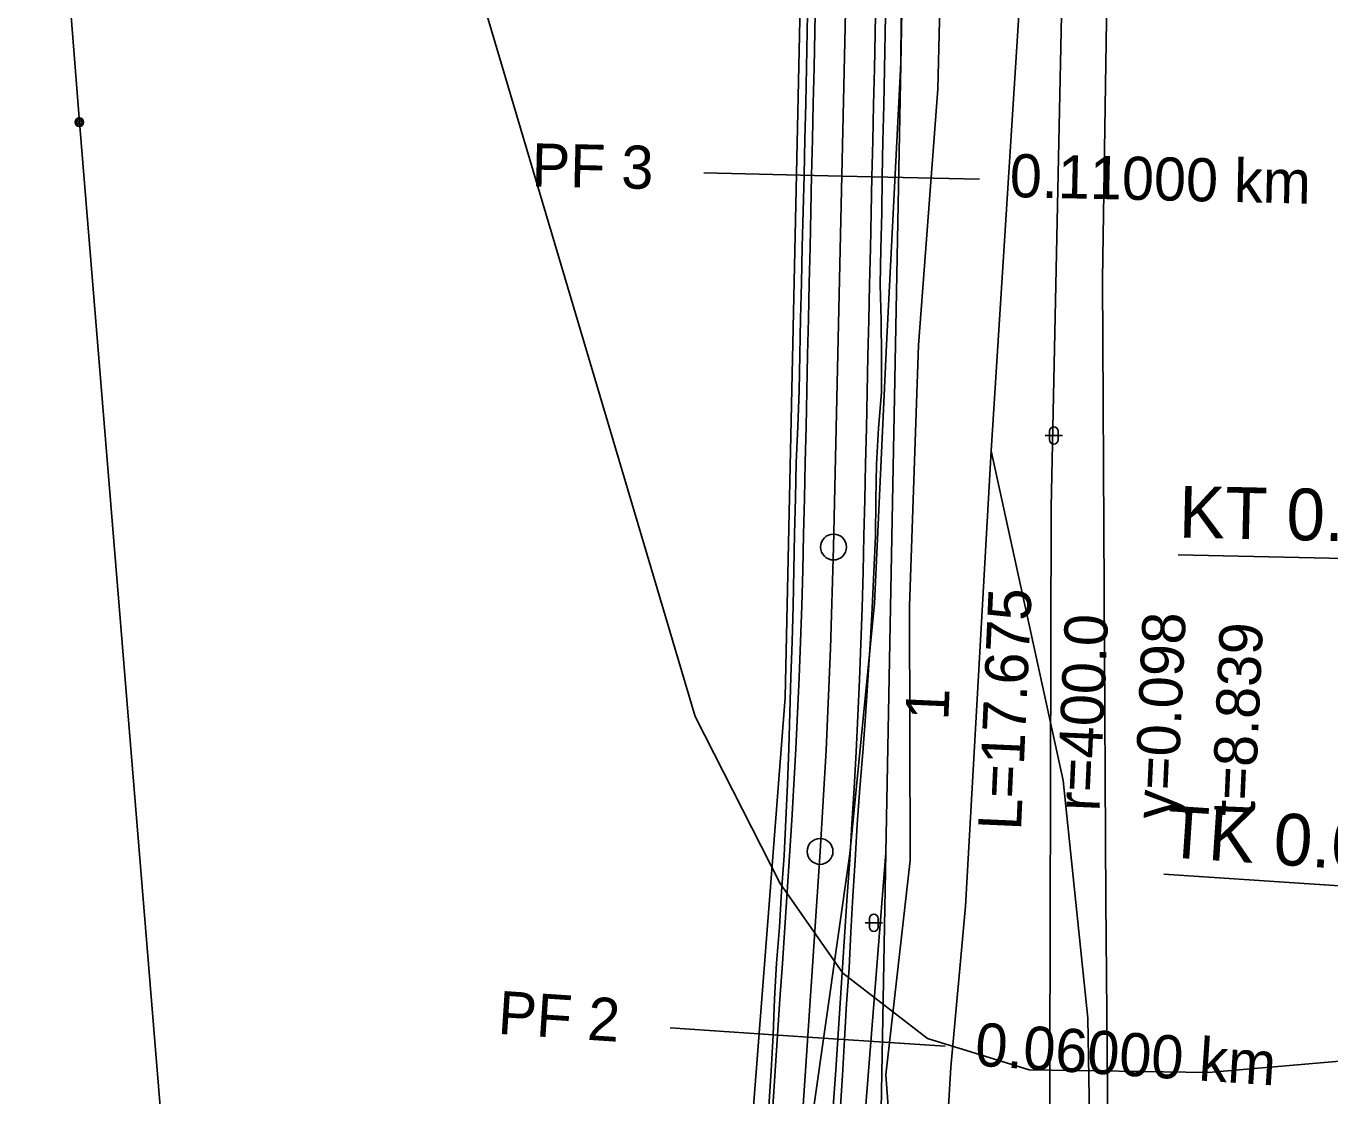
# Model space of a CAD drawing. Extents: x -555887 to -552101, y -1100251 to -1096546.
# Drawn here: x -554258.9 to -554183.3, y -1097524.4 to -1097462.4 of the extents above; entities that cross this region are included whole.
import ezdxf

# ---------------------------------------------------------------- set-up
doc = ezdxf.new("R2010")
doc.units = 0
for name, color, linetype in [('07_ELEKTRO', 7, 'Continuous'), ('PARCELY_cesty', 7, 'Continuous'), ('PARCELY_VHO', 7, 'Continuous'), ('POLYGONY_SITUACE_PF', 7, 'Continuous'), ('POLYGONY_SITUACE_PF_POPISY', 7, 'Continuous'), ('POLYGONY_SITUACE_PO', 7, 'Continuous'), ('vrstevnice', 7, 'Continuous'), ('ZSST', 7, 'Continuous')]:
    doc.layers.add(name, color=color, linetype=linetype)

msp = doc.modelspace()

# ---------------------------------------------------------------- linework, layer by layer
for p, q in [((-554192.078, -1097493.05), (-554170.991, -1097493.52)), ((-554192.901, -1097511.589), (-554171.855, -1097512.989))]:
    msp.add_line(p, q)
at = {"layer": '07_ELEKTRO'}
msp.add_lwpolyline([(-554275.08, -1097225.88), (-554271.756, -1097269.822), (-554266.687, -1097333.7), (-554260.452, -1097409.538), (-554255.844, -1097467.957), (-554251.063, -1097526.238), (-554246.538, -1097579.501), (-554242.27, -1097628.74), (-554241.833, -1097636.183)], dxfattribs=at)
at = {"layer": 'PARCELY_cesty'}
for points in [[(-554222.14, -1097577.67), (-554219.8, -1097564.758), (-554214.877, -1097501.328), (-554212.926, -1097411.068), (-554213.817, -1097399.017), (-554215.271, -1097391.192), (-554218.761, -1097379.641), (-554223.516, -1097368.495), (-554249.09, -1097318.382), (-554253.811, -1097305.999), (-554255.45, -1097297.231), (-554257.683, -1097277.564), (-554257.68, -1097272.957), (-554254.776, -1097263.93), (-554248.284, -1097256.84), (-554243.382, -1097252.09), (-554241.284, -1097247.986), (-554240.159, -1097243.281), (-554227.326, -1097094.829)], [(-554213.98, -1097572.5), (-554209.03, -1097510.351), (-554207.05, -1097405.63), (-554208.48, -1097387.75), (-554231.63, -1097341.59), (-554244.514, -1097316.349), (-554248.979, -1097304.638), (-554250.502, -1097296.489), (-554252.683, -1097277.283), (-554252.68, -1097273.743), (-554250.86, -1097269.06), (-554235.26, -1097250.21), (-554222.331, -1097095.103)]]:
    msp.add_lwpolyline(points, dxfattribs=at)
at = {"layer": 'PARCELY_VHO'}
msp.add_lwpolyline([(-554229.55, -1097316.95), (-554223.69, -1097322.98), (-554219.67, -1097327.12), (-554220.87, -1097341.28), (-554215.59, -1097358.86), (-554199.78, -1097386.16), (-554197.66, -1097405.58), (-554199.45, -1097490.3), (-554199.63, -1097570.97), (-554210.4, -1097572.11), (-554209.84, -1097554.02), (-554209.03, -1097510.351), (-554207.05, -1097405.63), (-554208.48, -1097387.75), (-554231.63, -1097341.59)], close=True, dxfattribs=at)
at = {"layer": 'POLYGONY_SITUACE_PF'}
for p, q in [((-554219.592, -1097470.904), (-554211.593, -1097471.082)), ((-554211.593, -1097471.082), (-554203.595, -1097471.261)), ((-554221.557, -1097520.503), (-554213.574, -1097521.034)), ((-554213.574, -1097521.034), (-554205.592, -1097521.566))]:
    msp.add_line(p, q, dxfattribs=at)
at = {"layer": 'POLYGONY_SITUACE_PO'}
for p, q in [((-554212.073, -1097492.604), (-554210.346, -1097415.119)), ((-554213.6, -1097462.702), (-554213.556, -1097460.619)), ((-554213.157, -1097462.712), (-554213.111, -1097460.629)), ((-554213.157, -1097462.712), (-554213.111, -1097460.629)), ((-554209.658, -1097462.79), (-554209.612, -1097460.707)), ((-554209.658, -1097462.79), (-554209.612, -1097460.707)), ((-554209.071, -1097462.803), (-554209.031, -1097460.72)), ((-554213.645, -1097464.785), (-554213.6, -1097462.702)), ((-554213.204, -1097464.795), (-554213.157, -1097462.712)), ((-554213.204, -1097464.795), (-554213.157, -1097462.712)), ((-554209.705, -1097464.873), (-554209.658, -1097462.79)), ((-554209.705, -1097464.873), (-554209.658, -1097462.79)), ((-554209.119, -1097464.886), (-554209.071, -1097462.803)), ((-554213.689, -1097466.868), (-554213.645, -1097464.785)), ((-554213.25, -1097466.878), (-554213.204, -1097464.795)), ((-554213.25, -1097466.878), (-554213.204, -1097464.795)), ((-554209.751, -1097466.956), (-554209.705, -1097464.873)), ((-554209.751, -1097466.956), (-554209.705, -1097464.873)), ((-554209.164, -1097466.969), (-554209.119, -1097464.886)), ((-554213.734, -1097468.951), (-554213.689, -1097466.868)), ((-554213.297, -1097468.961), (-554213.25, -1097466.878)), ((-554213.297, -1097468.961), (-554213.25, -1097466.878)), ((-554209.798, -1097469.038), (-554209.751, -1097466.956)), ((-554209.798, -1097469.038), (-554209.751, -1097466.956)), ((-554209.206, -1097469.052), (-554209.164, -1097466.969)), ((-554213.782, -1097471.034), (-554213.734, -1097468.951)), ((-554213.343, -1097471.043), (-554213.297, -1097468.961)), ((-554213.343, -1097471.043), (-554213.297, -1097468.961)), ((-554209.844, -1097471.121), (-554209.798, -1097469.038)), ((-554209.844, -1097471.121), (-554209.798, -1097469.038)), ((-554209.243, -1097471.135), (-554209.206, -1097469.052)), ((-554213.834, -1097473.116), (-554213.782, -1097471.034)), ((-554213.389, -1097473.126), (-554213.343, -1097471.043)), ((-554213.389, -1097473.126), (-554213.343, -1097471.043)), ((-554209.89, -1097473.204), (-554209.844, -1097471.121)), ((-554209.89, -1097473.204), (-554209.844, -1097471.121)), ((-554209.273, -1097473.218), (-554209.243, -1097471.135)), ((-554213.888, -1097475.199), (-554213.834, -1097473.116)), ((-554213.436, -1097475.209), (-554213.389, -1097473.126)), ((-554213.436, -1097475.209), (-554213.389, -1097473.126)), ((-554209.937, -1097475.287), (-554209.89, -1097473.204)), ((-554209.937, -1097475.287), (-554209.89, -1097473.204)), ((-554209.32, -1097475.301), (-554209.273, -1097473.218)), ((-554213.942, -1097477.282), (-554213.888, -1097475.199)), ((-554213.482, -1097477.292), (-554213.436, -1097475.209)), ((-554213.482, -1097477.292), (-554213.436, -1097475.209)), ((-554209.983, -1097477.37), (-554209.937, -1097475.287)), ((-554209.983, -1097477.37), (-554209.937, -1097475.287)), ((-554209.359, -1097477.384), (-554209.32, -1097475.301)), ((-554213.984, -1097479.364), (-554213.942, -1097477.282)), ((-554213.529, -1097479.375), (-554213.482, -1097477.292)), ((-554213.529, -1097479.375), (-554213.482, -1097477.292)), ((-554210.03, -1097479.453), (-554209.983, -1097477.37)), ((-554210.03, -1097479.453), (-554209.983, -1097477.37)), ((-554209.313, -1097479.469), (-554209.359, -1097477.384)), ((-554214.023, -1097481.447), (-554213.984, -1097479.364)), ((-554213.575, -1097481.457), (-554213.529, -1097479.375)), ((-554213.575, -1097481.457), (-554213.529, -1097479.375)), ((-554210.076, -1097481.535), (-554210.03, -1097479.453)), ((-554210.076, -1097481.535), (-554210.03, -1097479.453)), ((-554209.287, -1097481.553), (-554209.313, -1097479.469)), ((-554214.071, -1097483.53), (-554214.023, -1097481.447)), ((-554213.622, -1097483.54), (-554213.575, -1097481.457)), ((-554213.622, -1097483.54), (-554213.575, -1097481.457)), ((-554210.122, -1097483.618), (-554210.076, -1097481.535)), ((-554210.122, -1097483.618), (-554210.076, -1097481.535)), ((-554209.284, -1097483.637), (-554209.287, -1097481.553)), ((-554214.155, -1097485.612), (-554214.071, -1097483.53)), ((-554213.668, -1097485.623), (-554213.622, -1097483.54)), ((-554213.668, -1097485.623), (-554213.622, -1097483.54)), ((-554210.169, -1097485.701), (-554210.122, -1097483.618)), ((-554210.169, -1097485.701), (-554210.122, -1097483.618)), ((-554209.465, -1097485.717), (-554209.284, -1097483.637)), ((-554214.236, -1097487.694), (-554214.155, -1097485.612)), ((-554213.714, -1097487.706), (-554213.668, -1097485.623)), ((-554213.714, -1097487.706), (-554213.668, -1097485.623)), ((-554210.215, -1097487.784), (-554210.169, -1097485.701)), ((-554210.215, -1097487.784), (-554210.169, -1097485.701)), ((-554209.577, -1097487.798), (-554209.465, -1097485.717)), ((-554214.284, -1097489.777), (-554214.236, -1097487.694)), ((-554213.761, -1097489.789), (-554213.714, -1097487.706)), ((-554213.761, -1097489.789), (-554213.714, -1097487.706)), ((-554210.262, -1097489.867), (-554210.215, -1097487.784)), ((-554210.262, -1097489.867), (-554210.215, -1097487.784)), ((-554209.613, -1097489.881), (-554209.577, -1097487.798)), ((-554214.334, -1097491.86), (-554214.284, -1097489.777)), ((-554213.807, -1097491.871), (-554213.761, -1097489.789)), ((-554213.807, -1097491.871), (-554213.761, -1097489.789)), ((-554210.308, -1097491.949), (-554210.262, -1097489.867)), ((-554210.308, -1097491.949), (-554210.262, -1097489.867)), ((-554209.637, -1097491.964), (-554209.613, -1097489.881)), ((-554214.382, -1097493.935), (-554214.334, -1097491.86)), ((-554213.86, -1097493.948), (-554213.807, -1097491.871)), ((-554213.86, -1097493.948), (-554213.807, -1097491.871)), ((-554210.361, -1097494.038), (-554210.308, -1097491.949)), ((-554210.361, -1097494.038), (-554210.308, -1097491.949)), ((-554209.734, -1097494.054), (-554209.637, -1097491.964)), ((-554212.248, -1097498.493), (-554212.073, -1097492.604)), ((-554214.425, -1097496.006), (-554214.382, -1097493.935)), ((-554213.915, -1097496.022), (-554213.86, -1097493.948)), ((-554213.915, -1097496.022), (-554213.86, -1097493.948)), ((-554210.417, -1097496.13), (-554210.361, -1097494.038)), ((-554210.417, -1097496.13), (-554210.361, -1097494.038)), ((-554209.835, -1097496.148), (-554209.734, -1097494.054)), ((-554214.484, -1097498.077), (-554214.425, -1097496.006)), ((-554213.987, -1097498.095), (-554213.915, -1097496.022)), ((-554213.987, -1097498.095), (-554213.915, -1097496.022)), ((-554210.489, -1097498.221), (-554210.417, -1097496.13)), ((-554210.489, -1097498.221), (-554210.417, -1097496.13)), ((-554209.953, -1097498.24), (-554209.835, -1097496.148)), ((-554214.549, -1097500.147), (-554214.484, -1097498.077)), ((-554214.068, -1097500.167), (-554213.987, -1097498.095)), ((-554214.068, -1097500.167), (-554213.987, -1097498.095)), ((-554212.509, -1097504.379), (-554212.248, -1097498.493)), ((-554210.571, -1097500.312), (-554210.489, -1097498.221)), ((-554210.571, -1097500.312), (-554210.489, -1097498.221)), ((-554210.081, -1097500.332), (-554209.953, -1097498.24)), ((-554214.603, -1097502.219), (-554214.549, -1097500.147)), ((-554214.16, -1097502.239), (-554214.068, -1097500.167)), ((-554214.16, -1097502.239), (-554214.068, -1097500.167)), ((-554210.664, -1097502.402), (-554210.571, -1097500.312)), ((-554210.664, -1097502.402), (-554210.571, -1097500.312)), ((-554210.221, -1097502.423), (-554210.081, -1097500.332)), ((-554214.672, -1097504.29), (-554214.603, -1097502.219)), ((-554214.26, -1097504.311), (-554214.16, -1097502.239)), ((-554214.26, -1097504.311), (-554214.16, -1097502.239)), ((-554210.765, -1097504.492), (-554210.664, -1097502.402)), ((-554210.765, -1097504.492), (-554210.664, -1097502.402)), ((-554210.374, -1097504.513), (-554210.221, -1097502.423)), ((-554214.751, -1097506.361), (-554214.672, -1097504.29)), ((-554214.371, -1097506.382), (-554214.26, -1097504.311)), ((-554214.371, -1097506.382), (-554214.26, -1097504.311)), ((-554212.857, -1097510.26), (-554212.509, -1097504.379)), ((-554210.877, -1097506.582), (-554210.765, -1097504.492)), ((-554210.877, -1097506.582), (-554210.765, -1097504.492)), ((-554210.55, -1097506.6), (-554210.374, -1097504.513)), ((-554214.846, -1097508.431), (-554214.751, -1097506.361)), ((-554214.499, -1097508.453), (-554214.371, -1097506.382)), ((-554214.499, -1097508.453), (-554214.371, -1097506.382)), ((-554211.006, -1097508.67), (-554210.877, -1097506.582)), ((-554211.006, -1097508.67), (-554210.877, -1097506.582)), ((-554210.698, -1097508.689), (-554210.55, -1097506.6)), ((-554214.944, -1097510.503), (-554214.846, -1097508.431)), ((-554214.628, -1097510.524), (-554214.499, -1097508.453)), ((-554214.628, -1097510.524), (-554214.499, -1097508.453)), ((-554211.136, -1097510.757), (-554211.006, -1097508.67)), ((-554211.136, -1097510.757), (-554211.006, -1097508.67)), ((-554210.825, -1097510.778), (-554210.698, -1097508.689)), ((-554217.559, -1097580.902), (-554212.857, -1097510.26)), ((-554215.093, -1097512.581), (-554214.944, -1097510.503)), ((-554214.767, -1097512.603), (-554214.628, -1097510.524)), ((-554214.767, -1097512.603), (-554214.628, -1097510.524)), ((-554211.275, -1097512.836), (-554211.136, -1097510.757)), ((-554211.275, -1097512.836), (-554211.136, -1097510.757)), ((-554210.956, -1097512.857), (-554210.825, -1097510.778)), ((-554215.208, -1097514.662), (-554215.093, -1097512.581)), ((-554214.905, -1097514.682), (-554214.767, -1097512.603)), ((-554214.905, -1097514.682), (-554214.767, -1097512.603)), ((-554211.413, -1097514.914), (-554211.275, -1097512.836)), ((-554211.413, -1097514.914), (-554211.275, -1097512.836)), ((-554211.075, -1097514.937), (-554210.956, -1097512.857)), ((-554215.379, -1097516.738), (-554215.208, -1097514.662)), ((-554215.044, -1097516.761), (-554214.905, -1097514.682)), ((-554215.044, -1097516.761), (-554214.905, -1097514.682)), ((-554211.551, -1097516.993), (-554211.413, -1097514.914)), ((-554211.551, -1097516.993), (-554211.413, -1097514.914)), ((-554211.165, -1097517.019), (-554211.075, -1097514.937)), ((-554215.495, -1097518.819), (-554215.379, -1097516.738)), ((-554215.182, -1097518.839), (-554215.044, -1097516.761)), ((-554215.182, -1097518.839), (-554215.044, -1097516.761)), ((-554211.69, -1097519.072), (-554211.551, -1097516.993)), ((-554211.69, -1097519.072), (-554211.551, -1097516.993)), ((-554211.326, -1097519.096), (-554211.165, -1097517.019)), ((-554215.582, -1097520.901), (-554215.495, -1097518.819)), ((-554215.32, -1097520.918), (-554215.182, -1097518.839)), ((-554215.32, -1097520.918), (-554215.182, -1097518.839)), ((-554211.828, -1097521.151), (-554211.69, -1097519.072)), ((-554211.828, -1097521.151), (-554211.69, -1097519.072)), ((-554211.444, -1097521.176), (-554211.326, -1097519.096)), ((-554215.685, -1097522.982), (-554215.582, -1097520.901)), ((-554215.459, -1097522.997), (-554215.32, -1097520.918)), ((-554215.459, -1097522.997), (-554215.32, -1097520.918)), ((-554211.966, -1097523.229), (-554211.828, -1097521.151)), ((-554211.966, -1097523.229), (-554211.828, -1097521.151)), ((-554211.545, -1097523.257), (-554211.444, -1097521.176)), ((-554215.819, -1097525.061), (-554215.685, -1097522.982)), ((-554215.597, -1097525.076), (-554215.459, -1097522.997)), ((-554215.597, -1097525.076), (-554215.459, -1097522.997)), ((-554212.105, -1097525.308), (-554211.966, -1097523.229)), ((-554212.105, -1097525.308), (-554211.966, -1097523.229)), ((-554211.684, -1097525.336), (-554211.545, -1097523.257))]:
    msp.add_line(p, q, dxfattribs=at)
for centre in [(-554212.073, -1097492.604), (-554212.857, -1097510.26)]:
    msp.add_circle(centre, 0.75, dxfattribs=at)
at = {"layer": 'vrstevnice'}
msp.add_lwpolyline([(-554443.499, -1097167.35), (-554428.329, -1097192.26), (-554413.309, -1097220.06), (-554400.529, -1097238.88), (-554391.259, -1097249.97), (-554390.419, -1097250.25), (-554390.559, -1097251.09), (-554364.869, -1097276.65), (-554344.929, -1097292.8), (-554344.929, -1097293.36), (-554328.779, -1097306.56), (-554297.469, -1097333.8), (-554286.799, -1097344.33), (-554279.209, -1097353.74), (-554266.009, -1097373.68), (-554261.799, -1097382.1), (-554233.019, -1097458.91), (-554220.099, -1097502.44), (-554215.179, -1097512.13), (-554211.529, -1097517.32), (-554206.619, -1097521.11), (-554200.719, -1097522.94), (-554190.329, -1097523.08), (-554168.989, -1097521.25)], dxfattribs=at)
at = {"layer": 'ZSST'}
for p, q in [((-554207.15, -1097480.9), (-554207.66, -1097496.04)), ((-554199.543, -1097486.383), (-554199.541, -1097485.883)), ((-554199.043, -1097486.386), (-554199.041, -1097485.886)), ((-554198.792, -1097486.137), (-554199.792, -1097486.132)), ((-554204.42, -1097513.44), (-554202.93, -1097487.02)), ((-554207.62, -1097510.78), (-554207.66, -1097496.04)), ((-554209.234, -1097514.398), (-554210.234, -1097514.398)), ((-554209.984, -1097514.648), (-554209.984, -1097514.148)), ((-554209.484, -1097514.648), (-554209.484, -1097514.148))]:
    msp.add_line(p, q, dxfattribs=at)
for points in [[(-554271.756, -1097269.822), (-554266.687, -1097333.7), (-554260.452, -1097409.538), (-554255.844, -1097467.957), (-554251.063, -1097526.238), (-554246.538, -1097579.501)], [(-554228.49, -1097352.37), (-554222.31, -1097363.01), (-554217.16, -1097374.36), (-554213.13, -1097385.57), (-554210.33, -1097398.65), (-554208.63, -1097418.22), (-554207.9, -1097433.97), (-554208.03, -1097446.11), (-554208.17, -1097464.51), (-554209, -1097480.88), (-554209.7, -1097495.88), (-554211.13, -1097510.41), (-554213.95, -1097530.24)], [(-554207.41, -1097353.78), (-554209.41, -1097355.86), (-554201.48, -1097374.67), (-554195.3, -1097392.67), (-554195.74, -1097430.8), (-554196.46, -1097477.06)], [(-554207.15, -1097480.9), (-554206.03, -1097466.04), (-554205.54, -1097446.11), (-554205.17, -1097432.98), (-554205.64, -1097419.43), (-554206.7, -1097410.18), (-554204.44, -1097399.41), (-554206.31, -1097392.33), (-554207.77, -1097384.58), (-554210.25, -1097381.02), (-554214.71, -1097370.71), (-554222.07, -1097357.12)], [(-554209.43, -1097573.52), (-554199.51, -1097572.48), (-554196.92, -1097566.29), (-554196.91, -1097543.98), (-554197.32, -1097519.93), (-554198.74, -1097506.15), (-554202.93, -1097487.02), (-554201.29, -1097461.13), (-554201.38, -1097435.75)], [(-554196.46, -1097477.06), (-554196.27, -1097513.11), (-554195.97, -1097547.77)], [(-554210.15, -1097554.35), (-554209.75, -1097553.93), (-554209.6, -1097548), (-554209.52, -1097544.7), (-554208.51, -1097530.26), (-554209.04, -1097523.22), (-554207.62, -1097510.78)], [(-554204.42, -1097513.44), (-554205.27, -1097522.77), (-554206.79, -1097548.35)]]:
    msp.add_lwpolyline(points, dxfattribs=at)
for radius in [0.25, 0.158, 0.05]:
    msp.add_circle((-554255.844, -1097467.957), radius, dxfattribs=at)
for centre, start, end in [((-554199.291, -1097485.884), 359.7029, 179.7029), ((-554199.293, -1097486.384), 179.7029, 359.7029), ((-554209.734, -1097514.148), 0, 180), ((-554209.734, -1097514.648), 180, 0)]:
    msp.add_arc(centre, 0.25, start, end, dxfattribs=at)

# ---------------------------------------------------------------- texts
for s, height, rotation, p in [('KT 0.08847', 3, 358.72348, (-554192.056, -1097492.05)), ('L=17.675', 2.5, 87.45762, (-554201.195, -1097509.074)), ('r=400.0', 2.5, 87.45762, (-554196.642, -1097507.967)), ('y=0.098', 2.5, 87.45762, (-554192.157, -1097508.417)), ('t=8.839', 2.5, 87.45762, (-554187.646, -1097508.271)), ('1', 2.5, 87.45762, (-554205.416, -1097502.688)), ('TK 0.07080', 3, 356.19176, (-554192.835, -1097510.591))]:
    msp.add_text(s, height=height, rotation=rotation).set_placement(p)
at = {"layer": 'POLYGONY_SITUACE_PF_POPISY'}
for s, rotation, p in [('PF 3', 358.72348, (-554229.611, -1097471.681)), ('0.11000 km', 358.72348, (-554201.865, -1097472.299)), ('PF 2', 356.19176, (-554231.601, -1097520.837)), ('0.06000 km', 356.19176, (-554203.909, -1097522.68))]:
    msp.add_text(s, height=2.5, rotation=rotation, dxfattribs=at).set_placement(p)

doc.saveas('drawing.dxf')
